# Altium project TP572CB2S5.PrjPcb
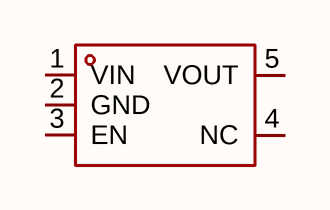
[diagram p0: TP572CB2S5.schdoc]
1 sheet, 1 parts. Net scope: global (net labels, ports and power ports of the same name join across sheets).

## Sheet TP572CB2S5.schdoc
size 127 x 101 mm

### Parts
U?  tp572cb2s5  [SOT-23-5_L3.0-W1.7-P0.95-LS2.8-BR]  (value not drawn)

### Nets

Not connected (* = marked no-connect by the designer): U? 1(VIN) 2(GND) 3(EN) 4(NC) 5(VOUT)

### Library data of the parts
U? = tp572cb2s5: 输出极性:正极;工作电压:60V;输出电压:12V;输出电流:200mA;电源纹波抑制比(PSRR):-;输出类型:固定;; Manufacturer: TECH PUBLIC(台舟); AddInBom: yes; ModelId: 0a2a1b8f50944f73965918ad6e5fe167; ModelName: SOT-23-5_L2.9-W1.6-H1.1-LS2.8-P0.95; ModelTransform: 114.173,109.636,0,180,0,0,0,0,0; Output Configuration: 正极; Voltage - Supply: 60V; Output Voltage: 12V; Output Current: 200mA; Voltage Dropout: 660mV; standby current: 2uA; Output Type: 固定; Number of Outputs: 1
